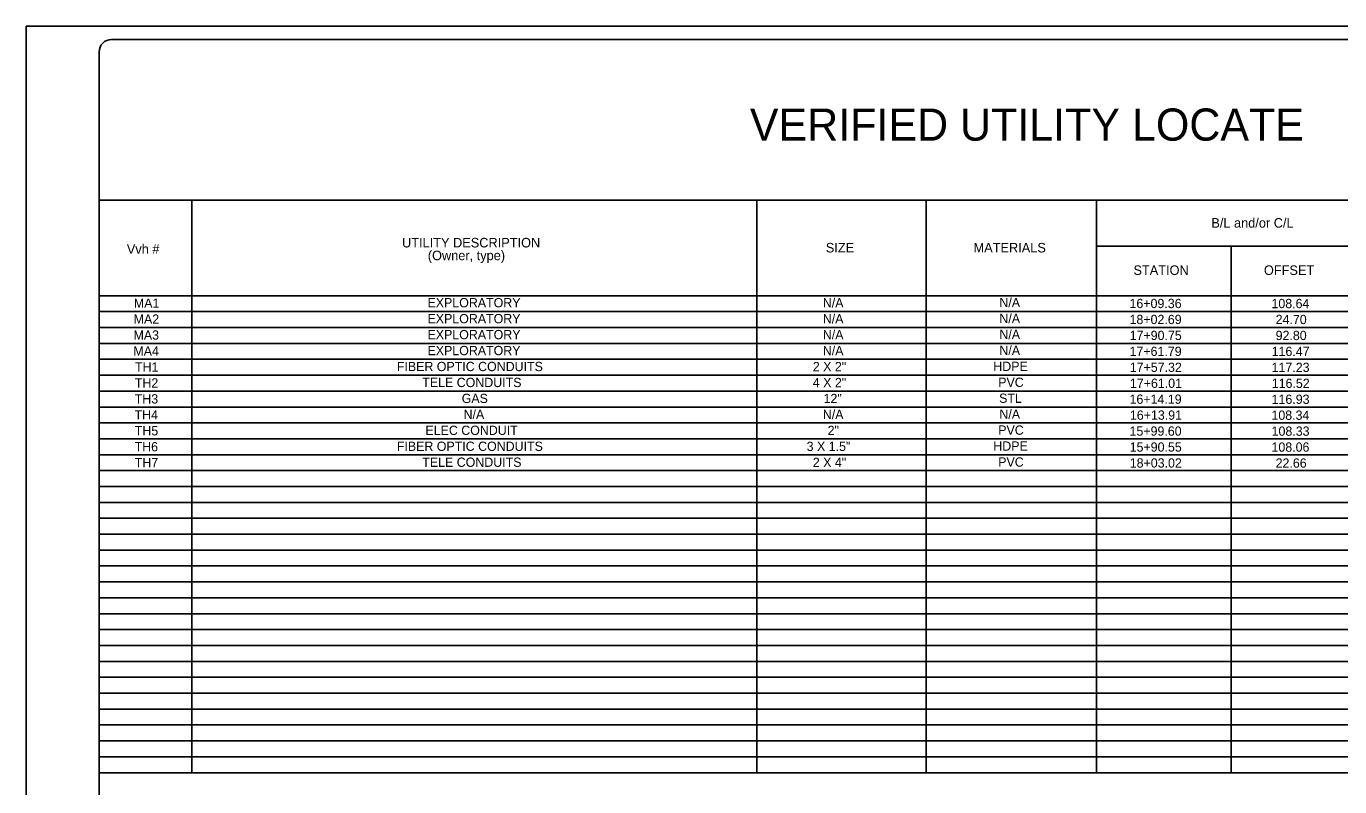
# Model space of a CAD drawing. Extents: x -769.4 to -731.2, y -2181.6 to -2171.
# Drawn here: x -749.13 to -739.22, y -2176.72 to -2170.98 of the extents above; entities that cross this region are included whole.
import ezdxf

# ---------------------------------------------------------------- set-up
doc = ezdxf.new("R2010")
doc.units = 0
for name, color, linetype in [('Default', 7, 'Continuous'), ('PlotBorder_dp', 7, 'Continuous'), ('TextSurveyLabel', 7, 'Continuous')]:
    doc.layers.add(name, color=color, linetype=linetype)

msp = doc.modelspace()

# ---------------------------------------------------------------- linework, layer by layer
at = {"layer": 'Default'}
for p, q in [((-733.2587, -2171.0816), (-748.4899, -2171.0816)), ((-748.5834, -2181.2893), (-748.5834, -2171.1752))]:
    msp.add_line(p, q, dxfattribs=at)
msp.add_ellipse((-748.4898, -2171.1751), major_axis=(0, -0.0935), ratio=0.999927, start_param=3.141593, end_param=4.712389, dxfattribs=at)
at = {"layer": 'PlotBorder_dp'}
msp.add_lwpolyline([(-749.1334, -2181.5815), (-732.6334, -2181.5815), (-732.6334, -2170.9815), (-749.1334, -2170.9815)], close=True, dxfattribs=at)
at = {"layer": 'TextSurveyLabel'}
for p, q in [((-748.5834, -2172.2929), (-733.1834, -2172.2929)), ((-748.5434, -2172.2929), (-733.1834, -2172.2929)), ((-747.8824, -2172.2929), (-747.8824, -2176.6153)), ((-743.619, -2172.2929), (-743.619, -2176.6153)), ((-742.339, -2172.2929), (-742.339, -2176.6153)), ((-741.0549, -2172.2929), (-741.0549, -2176.6153)), ((-741.0549, -2172.6404), (-738.4807, -2172.6404)), ((-740.0387, -2172.6404), (-740.0387, -2176.6153)), ((-748.5834, -2173.0153), (-733.1834, -2173.0153)), ((-748.5834, -2173.1354), (-733.1834, -2173.1354)), ((-748.5834, -2173.2553), (-733.1834, -2173.2553)), ((-748.5834, -2173.3752), (-733.1834, -2173.3752)), ((-748.5834, -2173.4953), (-733.1834, -2173.4953)), ((-748.5834, -2173.6154), (-733.1834, -2173.6154)), ((-748.5834, -2173.7353), (-733.1834, -2173.7353)), ((-748.5834, -2173.8552), (-733.1834, -2173.8552)), ((-748.5834, -2173.9753), (-733.1834, -2173.9753)), ((-748.5834, -2174.0954), (-733.1834, -2174.0954)), ((-748.5834, -2174.2153), (-733.1834, -2174.2153)), ((-748.5834, -2174.3352), (-733.1834, -2174.3352)), ((-748.5834, -2174.4553), (-733.1834, -2174.4553)), ((-748.5834, -2174.5754), (-733.1834, -2174.5754)), ((-748.5834, -2174.6953), (-733.1834, -2174.6953)), ((-748.5834, -2174.8154), (-733.1834, -2174.8154)), ((-748.5834, -2174.9353), (-733.1834, -2174.9353)), ((-748.5834, -2175.0552), (-733.1834, -2175.0552)), ((-748.5834, -2175.1753), (-733.1834, -2175.1753)), ((-748.5834, -2175.2954), (-733.1834, -2175.2954)), ((-748.5834, -2175.4153), (-733.1834, -2175.4153)), ((-748.5834, -2175.5352), (-733.1834, -2175.5352)), ((-748.5834, -2175.6553), (-733.1834, -2175.6553)), ((-748.5834, -2175.7754), (-733.1834, -2175.7754)), ((-748.5834, -2175.8953), (-733.1834, -2175.8953)), ((-748.5834, -2176.0152), (-733.1834, -2176.0152)), ((-748.5834, -2176.1353), (-733.1834, -2176.1353)), ((-748.5834, -2176.2554), (-733.1834, -2176.2554)), ((-748.5834, -2176.3753), (-733.1834, -2176.3753)), ((-748.5834, -2176.4954), (-733.1834, -2176.4954)), ((-748.5834, -2176.6153), (-733.1834, -2176.6153))]:
    msp.add_line(p, q, dxfattribs=at)

# ---------------------------------------------------------------- texts
for s, height, p in [('   VERIFIED UTILITY LOCATE   ', 0.242647, (-743.9416, -2171.8448)), ('B/L and/or C/L', 0.072, (-740.1875, -2172.5014)), ('UTILITY DESCRIPTION', 0.072, (-746.2969, -2172.6508)), ('Vvh #', 0.072, (-748.3743, -2172.6989)), ('(Owner, type)', 0.072, (-746.1022, -2172.747)), ('SIZE', 0.072, (-743.0978, -2172.6887)), ('MATERIALS', 0.072, (-741.9824, -2172.6887)), ('STATION', 0.072, (-740.7755, -2172.8584)), ('OFFSET', 0.072, (-739.7906, -2172.8584)), ('MA1', 0.07, (-748.3214, -2173.1064)), ('EXPLORATORY', 0.07, (-746.1045, -2173.1028)), ('N/A', 0.07, (-743.1204, -2173.1036)), ('N/A', 0.07, (-741.7874, -2173.1014)), ('16+09.36  ', 0.07, (-740.8052, -2173.1089)), ('108.64', 0.07, (-739.7337, -2173.1092)), ('MA2', 0.07, (-748.3226, -2173.2268)), ('EXPLORATORY', 0.07, (-746.1045, -2173.2232)), ('N/A', 0.07, (-743.1204, -2173.224)), ('N/A', 0.07, (-741.7874, -2173.2218)), ('18+02.69', 0.07, (-740.8049, -2173.2293)), ('24.70', 0.07, (-739.7021, -2173.2296)), ('N/A', 0.07, (-743.1204, -2173.3444)), ('N/A', 0.07, (-741.7874, -2173.3422)), ('MA3', 0.07, (-748.3236, -2173.3472)), ('EXPLORATORY', 0.07, (-746.1045, -2173.3436)), ('17+90.75', 0.07, (-740.804, -2173.3496)), ('92.80', 0.07, (-739.7021, -2173.35)), ('MA4', 0.07, (-748.3248, -2173.4676)), ('EXPLORATORY', 0.07, (-746.1045, -2173.464)), ('N/A', 0.07, (-743.1204, -2173.4648)), ('N/A', 0.07, (-741.7874, -2173.4626)), ('17+61.79', 0.07, (-740.8049, -2173.47)), ('116.47', 0.07, (-739.7322, -2173.4704)), ('TH1', 0.07, (-748.3124, -2173.588)), ('FIBER OPTIC CONDUITS', 0.07, (-746.3361, -2173.5844)), ('2 X 2"', 0.07, (-743.1958, -2173.5852)), ('HDPE', 0.07, (-741.8334, -2173.583)), ('17+57.32', 0.07, (-740.8034, -2173.5903)), ('117.23', 0.07, (-739.7325, -2173.5908)), ('TH2', 0.07, (-748.3136, -2173.7084)), ('TELE CONDUITS', 0.07, (-746.1441, -2173.7048)), ('4 X 2"', 0.07, (-743.1958, -2173.7056)), ('PVC', 0.07, (-741.7962, -2173.7034)), ('17+61.01', 0.07, (-740.8021, -2173.7107)), ('116.52', 0.07, (-739.7315, -2173.7112)), ('TH3', 0.07, (-748.3146, -2173.8288)), ('GAS ', 0.07, (-745.8463, -2173.8252)), ('12"', 0.07, (-743.1148, -2173.826)), ('STL', 0.07, (-741.7897, -2173.8238)), ('16+14.19', 0.07, (-740.8049, -2173.831)), ('116.93', 0.07, (-739.7325, -2173.8316)), ('TH4', 0.07, (-748.3158, -2173.9492)), ('N/A', 0.07, (-745.8322, -2173.9456)), ('N/A', 0.07, (-743.1204, -2173.9464)), ('N/A', 0.07, (-741.7874, -2173.9442)), ('16+13.91', 0.07, (-740.8021, -2173.9514)), ('108.34', 0.07, (-739.7337, -2173.952)), ('TH5', 0.07, (-748.3142, -2174.0696)), ('ELEC CONDUIT', 0.07, (-746.1202, -2174.066)), ('2"', 0.07, (-743.0838, -2174.0668)), ('PVC', 0.07, (-741.7962, -2174.0646)), ('15+99.60 ', 0.07, (-740.805, -2174.0718)), ('108.33', 0.07, (-739.7325, -2174.0724)), ('TH6', 0.07, (-748.3154, -2174.19)), ('FIBER OPTIC CONDUITS ', 0.07, (-746.3361, -2174.1864)), ('3 X 1.5"', 0.07, (-743.2424, -2174.1872)), ('HDPE', 0.07, (-741.8334, -2174.185)), ('15+90.55', 0.07, (-740.804, -2174.1921)), ('108.06', 0.07, (-739.7333, -2174.1928)), ('TH7', 0.07, (-748.3144, -2174.3104)), ('TELE CONDUITS', 0.07, (-746.1441, -2174.3068)), ('2 X 4"', 0.07, (-743.1958, -2174.3076)), ('PVC', 0.07, (-741.7962, -2174.3054)), ('18+03.02', 0.07, (-740.8034, -2174.3125)), ('22.66', 0.07, (-739.7023, -2174.3132))]:
    msp.add_text(s, height=height, dxfattribs=at).set_placement(p)

doc.saveas('drawing.dxf')
